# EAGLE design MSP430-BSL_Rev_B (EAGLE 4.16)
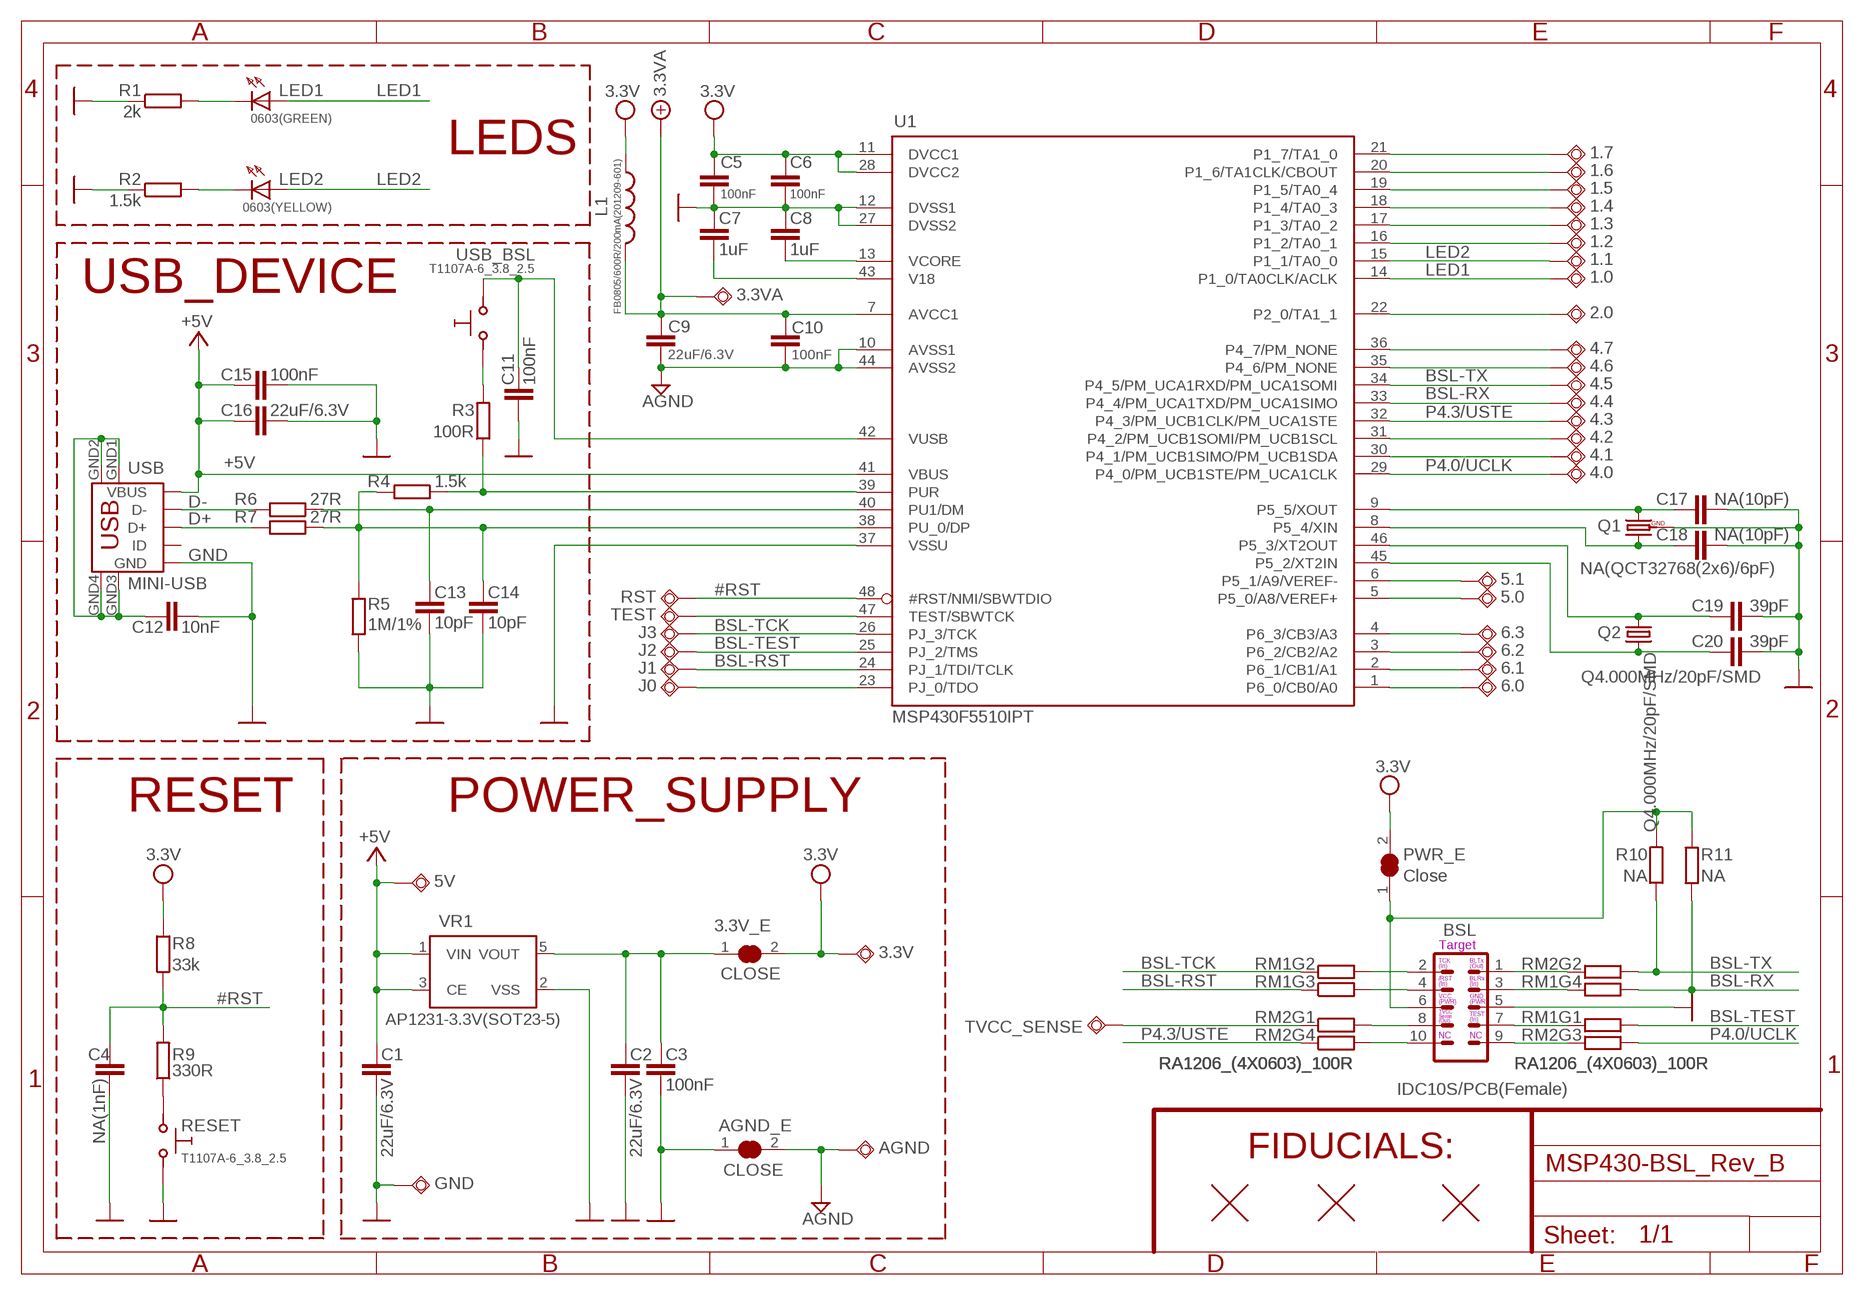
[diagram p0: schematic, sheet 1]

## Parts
1.0  TESTPAD80/50  [SMD80/50]
1.1  TESTPAD80/50  [SMD80/50]
1.2  TESTPAD80/50  [SMD80/50]
1.3  TESTPAD80/50  [SMD80/50]
1.4  TESTPAD80/50  [SMD80/50]
1.5  TESTPAD80/50  [SMD80/50]
1.6  TESTPAD80/50  [SMD80/50]
1.7  TESTPAD80/50  [SMD80/50]
2.0  TESTPAD80/50  [SMD80/50]
3.3V  TESTPAD80/50  [SMD80/50]
3.3V_E  CLOSE  SJSJ_1_SMALLER_CLOSE  [SJ_1_SMALLER_CLOSE]
3.3VA  TESTPAD80/50  [SMD80/50]
4.0  TESTPAD80/50  [SMD80/50]
4.1  TESTPAD80/50  [SMD80/50]
4.2  TESTPAD80/50  [SMD80/50]
4.3  TESTPAD80/50  [SMD80/50]
4.4  TESTPAD80/50  [SMD80/50]
4.5  TESTPAD80/50  [SMD80/50]
4.6  TESTPAD80/50  [SMD80/50]
4.7  TESTPAD80/50  [SMD80/50]
5.0  TESTPAD80/50  [SMD80/50]
5.1  TESTPAD80/50  [SMD80/50]
5V  TESTPAD80/50  [SMD80/50]
6.0  TESTPAD80/50  [SMD80/50]
6.1  TESTPAD80/50  [SMD80/50]
6.2  TESTPAD80/50  [SMD80/50]
6.3  TESTPAD80/50  [SMD80/50]
AGND  TESTPAD80/50  [SMD80/50]
AGND_E  CLOSE  SJSJ_1_SMALLER_CLOSE  [SJ_1_SMALLER_CLOSE]
BSL  IDC10S/PCB(Female)  ML10SMD_1  [ML10L_PADS_FEMAIL]
C1  22uF/6.3V  C-EUC0603_DWS  [C0603_DWS]
C2  22uF/6.3V  C-EUC0603_DWS  [C0603_DWS]
C3  100nF  C-EUC0603_DWS  [C0603_DWS]
C4  NA(1nF)  C-EUC0603_DWS  [C0603_DWS]
C5  100nF  C-EUC0603_DWS  [C0603_DWS]
C6  100nF  C-EUC0603_DWS  [C0603_DWS]
C7  1uF  C-EUC0603_DWS  [C0603_DWS]
C8  1uF  C-EUC0603_DWS  [C0603_DWS]
C9  22uF/6.3V  C-EUC0603_DWS  [C0603_DWS]
C10  100nF  C-EUC0603_DWS  [C0603_DWS]
C11  100nF  C-EUC0603_DWS  [C0603_DWS]
C12  10nF  C-EUC0603_DWS  [C0603_DWS]
C13  10pF  C-EUC0603_DWS  [C0603_DWS]
C14  10pF  C-EUC0603_DWS  [C0603_DWS]
C15  100nF  C-EUC0603_DWS  [C0603_DWS]
C16  22uF/6.3V  C-EUC0603_DWS  [C0603_DWS]
C17  NA(10pF)  C-EUC0603_DWS  [C0603_DWS]
C18  NA(10pF)  C-EUC0603_DWS  [C0603_DWS]
C19  39pF  C-EUC0603_DWS  [C0603_DWS]
C20  39pF  C-EUC0603_DWS  [C0603_DWS]
GND  TESTPAD80/50  [SMD80/50]
J0  TESTPAD80/50  [SMD80/50]
J1  TESTPAD80/50  [SMD80/50]
J2  TESTPAD80/50  [SMD80/50]
J3  TESTPAD80/50  [SMD80/50]
L1  FB0805/600R/200mA(201209-601)  L-USL0805_5MIL_DWS  [L0805_5MIL_DWS]
LED1  0603(GREEN)  LED0603DWS  [LED-0603]
LED2  0603(YELLOW)  LED0603DWS  [LED-0603]
PWR_E  Close  SJSJ_1_SMALLER_CLOSE  [SJ_1_SMALLER_CLOSE]
Q1  NA(QCT32768(2x6)/6pF)  Q_GND1  [TC26H_3_REPAIR_SMD]
Q2  Q4.000MHz/20pF/SMD  HC49/S1  [HC49/SMD2_THIN]
R1  2k  R-EU_R0603_5MIL_DWS  [R0603_5MIL_DWS]
R2  1.5k  R-EU_R0603_5MIL_DWS  [R0603_5MIL_DWS]
R3  100R  R-EU_R0603_5MIL_DWS  [R0603_5MIL_DWS]
R4  1.5k  R-EU_R0603_5MIL_DWS  [R0603_5MIL_DWS]
R5  1M/1%  R-EU_R0603_5MIL_DWS  [R0603_5MIL_DWS]
R6  27R  R-EU_R0603_5MIL_DWS  [R0603_5MIL_DWS]
R7  27R  R-EU_R0603_5MIL_DWS  [R0603_5MIL_DWS]
R8  33k  R-EU_R0603_5MIL_DWS  [R0603_5MIL_DWS]
R9  330R  R-EU_R0603_5MIL_DWS  [R0603_5MIL_DWS]
R10  NA  R-EU_R0603_5MIL_DWS  [R0603_5MIL_DWS]
R11  NA  R-EU_R0603_5MIL_DWS  [R0603_5MIL_DWS]
RESET  T1107A-6_3.8_2.5  SW-TAKT6  [SW-TAKT_6X3.5_SMD]
RM1  RA1206_(4X0603)_100R  R_MATRIX_4E  [R_MATRIX_4]
RM2  RA1206_(4X0603)_100R  R_MATRIX_4E  [R_MATRIX_4]
RST  TESTPAD80/50  [SMD80/50]
TEST  TESTPAD80/50  [SMD80/50]
TVCC_SENSE  TESTPAD80/50  [SMD80/50]
U1  MSP430F5510IPT  MSP430F5510  [S-PQFP-G48]
U$2  FIDUCIAL1X2  [FIDUCIAL-1X2]
U$500  FIDUCIAL1X2  [FIDUCIAL-1X2]
U$507  FIDUCIAL1X2  [FIDUCIAL-1X2]
USB  MINI-USB  MINI_USB9  [USB_MINI_9PIN]
USB_BSL  T1107A-6_3.8_2.5  SW-TAKT6  [SW-TAKT_6X3.5_SMD]
VR1  AP1231-3.3V(SOT23-5)  AP1231-33  [SOT-23-5]

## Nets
#RST: C4.2 R8.1 R9.2 RST.P$1(PP) U1.48(#RST/NMI/SBWTDIO)
+5V: 5V.P$1(PP) C1.1 C15.2 C16.2 U1.41(VBUS) USB.VBUS VR1.1(VIN) VR1.3(CE)
+8V: 3.3VA.P$1(PP) C9.1 C10.2 L1.2 U1.7(AVCC1) ; supply symbol labelled 3.3VA
AGND: AGND.P$1(PP) AGND_E.2 C9.2 C10.1 U1.10(AVSS1) U1.44(AVSS2)
BSL-RST: J1.P$1(PP) RM1.3.1 U1.24(PJ_1/TDI/TCLK)
BSL-RX: 4.4.P$1(PP) R11.2 RM1.4.1 U1.33(P4_4/PM_UCA1TXD/PM_UCA1SIMO)
BSL-TCK: J3.P$1(PP) RM1.2.1 U1.26(PJ_3/TCK)
BSL-TEST: J2.P$1(PP) RM1.1.1 U1.25(PJ_2/TMS)
BSL-TX: 4.5.P$1(PP) R10.2 RM2.2.1 U1.34(P4_5/PM_UCA1RXD/PM_UCA1SOMI)
D+: C14.2 R4.2 R5.1 R7.1 U1.38(PU_0/DP)
D-: C13.2 R6.1 U1.40(PU1/DM)
GND: AGND_E.1 BSL.5 C1.2 C2.2 C3.2 C4.1 C5.1 C6.1 C7.2 C8.2 C11.1 C12.1 C13.1 C14.1 C15.1 C16.1 C17.1 C18.1 C19.1 C20.1 GND.P$1(PP) Q1.GND R1.1 R2.1 R5.2 RESET.P$2 U1.12(DVSS1) U1.27(DVSS2) U1.37(VSSU) USB.GND VR1.2(VSS)
LED1: 1.0.P$1(PP) LED1.A U1.14(P1_0/TA0CLK/ACLK)
LED2: 1.1.P$1(PP) LED2.A U1.15(P1_1/TA0_0)
N$1: LED2.C R2.2
N$2: C19.2 Q2.1 U1.46(P5_3/XT2OUT)
N$3: BSL.10 RM2.4.2
N$4: BSL.8 RM2.1.2
N$5: R3.1 R4.1 U1.39(PUR)
N$6: BSL.9 RM2.3.2
N$7: 6.3.P$1(PP) U1.4(P6_3/CB3/A3)
N$8: C17.2 Q1.1 U1.9(P5_5/XOUT)
N$9: C18.2 Q1.2 U1.8(P5_4/XIN)
N$10: C20.2 Q2.2 U1.45(P5_2/XT2IN)
N$11: R9.1 RESET.P$1
N$12: BSL.1 RM2.2.2
N$13: LED1.C R1.2
N$14: BSL.2 RM1.2.2
N$15: BSL.3 RM1.4.2
N$16: BSL.4 RM1.3.2
N$17: 6.0.P$1(PP) U1.1(P6_0/CB0/A0)
N$18: R6.2 USB.D-
N$19: R3.2 USB_BSL.P$1
N$20: J0.P$1(PP) U1.23(PJ_0/TDO)
N$21: R7.2 USB.D+
N$22: BSL.7 RM1.1.2
N$23: RM2.1.1 TVCC_SENSE.P$1(PP)
P1.2: 1.2.P$1(PP) U1.16(P1_2/TA0_1)
P1.3: 1.3.P$1(PP) U1.17(P1_3/TA0_2)
P1.4: 1.4.P$1(PP) U1.18(P1_4/TA0_3)
P1.5: 1.5.P$1(PP) U1.19(P1_5/TA0_4)
P1.6: 1.6.P$1(PP) U1.20(P1_6/TA1CLK/CBOUT)
P1.7: 1.7.P$1(PP) U1.21(P1_7/TA1_0)
P2.0: 2.0.P$1(PP) U1.22(P2_0/TA1_1)
P4.0/UCLK: 4.0.P$1(PP) RM2.3.1 U1.29(P4_0/PM_UCB1STE/PM_UCA1CLK)
P4.1: 4.1.P$1(PP) U1.30(P4_1/PM_UCB1SIMO/PM_UCB1SDA)
P4.2: 4.2.P$1(PP) U1.31(P4_2/PM_UCB1SOMI/PM_UCB1SCL)
P4.3/USTE: 4.3.P$1(PP) RM2.4.1 U1.32(P4_3/PM_UCB1CLK/PM_UCA1STE)
P4.6: 4.6.P$1(PP) U1.35(P4_6/PM_NONE)
P4.7: 4.7.P$1(PP) U1.36(P4_7/PM_NONE)
P5.0: 5.0.P$1(PP) U1.5(P5_0/A8/VEREF+)
P5.1: 5.1.P$1(PP) U1.6(P5_1/A9/VEREF-)
P6.1: 6.1.P$1(PP) U1.2(P6_1/CB1/A1)
P6.2: 6.2.P$1(PP) U1.3(P6_2/CB2/A2)
TARGET_PWR: BSL.6 PWR_E.1 R10.1 R11.1
TEST: TEST.P$1(PP) U1.47(TEST/SBWTCK)
USB_SHIELD: C12.2 USB.GND1 USB.GND2 USB.GND3 USB.GND4
V18: C7.1 U1.43(V18)
VCC: 3.3V.P$1(PP) 3.3V_E.2 C5.2 C6.2 L1.1 PWR_E.2 R8.2 U1.11(DVCC1) U1.28(DVCC2) ; supply symbol labelled 3.3V
VCORE: C8.1 U1.13(VCORE)
VOUT: 3.3V_E.1 C2.1 C3.1 VR1.5(VOUT)
VUSB: C11.2 U1.42(VUSB) USB_BSL.P$2
Unconnected: USB.ID

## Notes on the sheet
- LEDS
- USB_DEVICE
- Q4.000MHz/20pF/SMD
- RESET | POWER_SUPPLY
- Target
- TCK | BLTx
- (In) | (Out)
- /RST | BLRx
- (In) | (In)
- VCC | GND
- (PWR) | (PWR)
- TVCC
- TEST
- Sense
- (Out) | (In)
- NC | NC
- FIDUCIALS:

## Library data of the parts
1.0 1.1-1.7 2.0 3.3V 3.3VA 4.0 4.1-4.7 5.0 5.1 5V 6.0 6.1-6.3 AGND GND J0 J1-J3 RST TEST TVCC_SENSE = gogo:TESTPAD: drill 40mils, diameter 70mils
3.3V_E AGND_E PWR_E = jumper:SJ: SMD solder JUMPER
BSL = con-harting-ml:ML10: HARTING
C1-C20 = rcl:C-EU: CAPACITOR, European symbol
L1 = rcl:L-US: INDUCTOR, American symbol
LED1 LED2 = DOUBLE-SIDE:LED
Q1 = crystal:Q_GND
Q2 = crystal:HC49/S: CRYSTAL
R1-R11 = rcl:R-EU_: RESISTOR, European symbol
RESET USB_BSL = gogo:SW-TAKT
RM1 RM2 = OLIMEX_DISCRET:R_MATRIX_4E
U1 = OLIMEX_IC:MSP430F5510
U$2 U$500 U$507 = SparkFunEagle-6-6-07:FIDUCIAL: Fiducial Alignment Points
USB = OLIMEX_CONNECTORS:MINI_USB9
VR1 = OLIMEX_DISCRET:AP1231

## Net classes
0 default: width 0.2 mm, drill 0.2 mm
1 pwr: width 0.35 mm, drill 0.25 mm
2 thin: width 0.025 mm, drill 0.025 mm

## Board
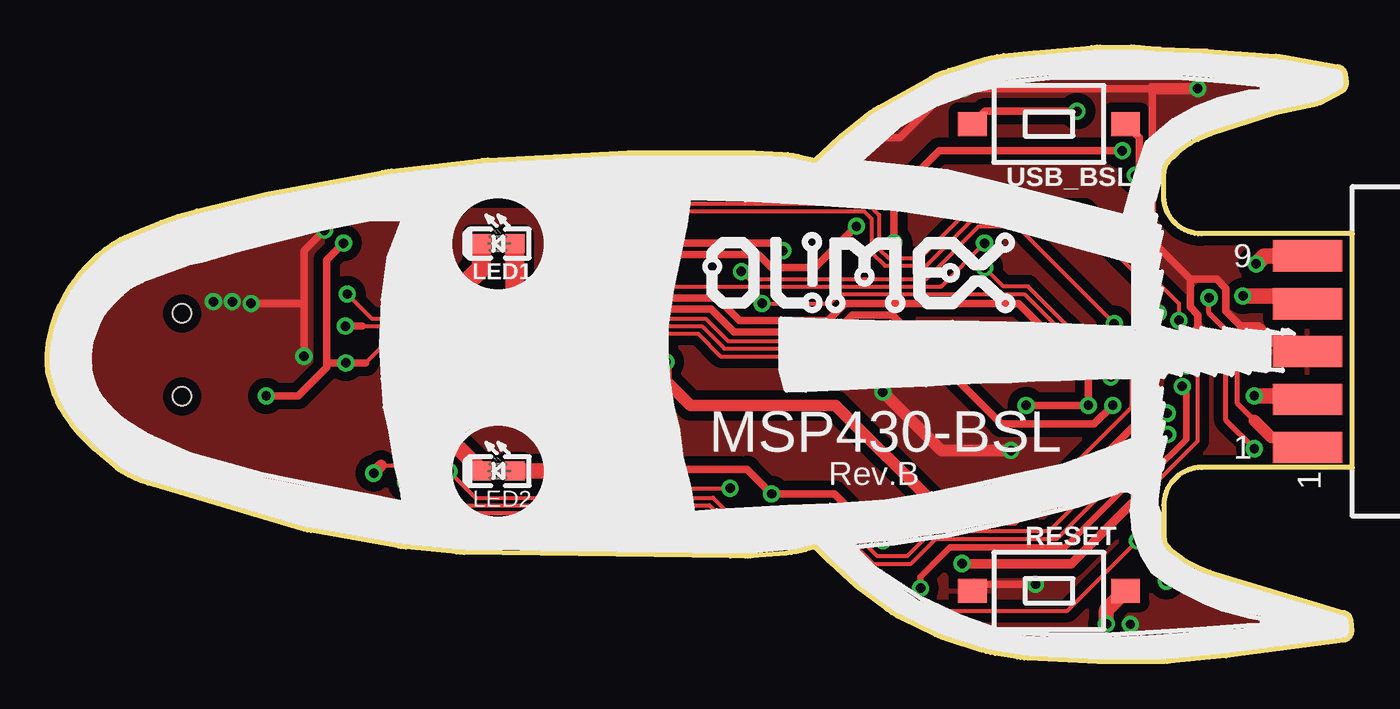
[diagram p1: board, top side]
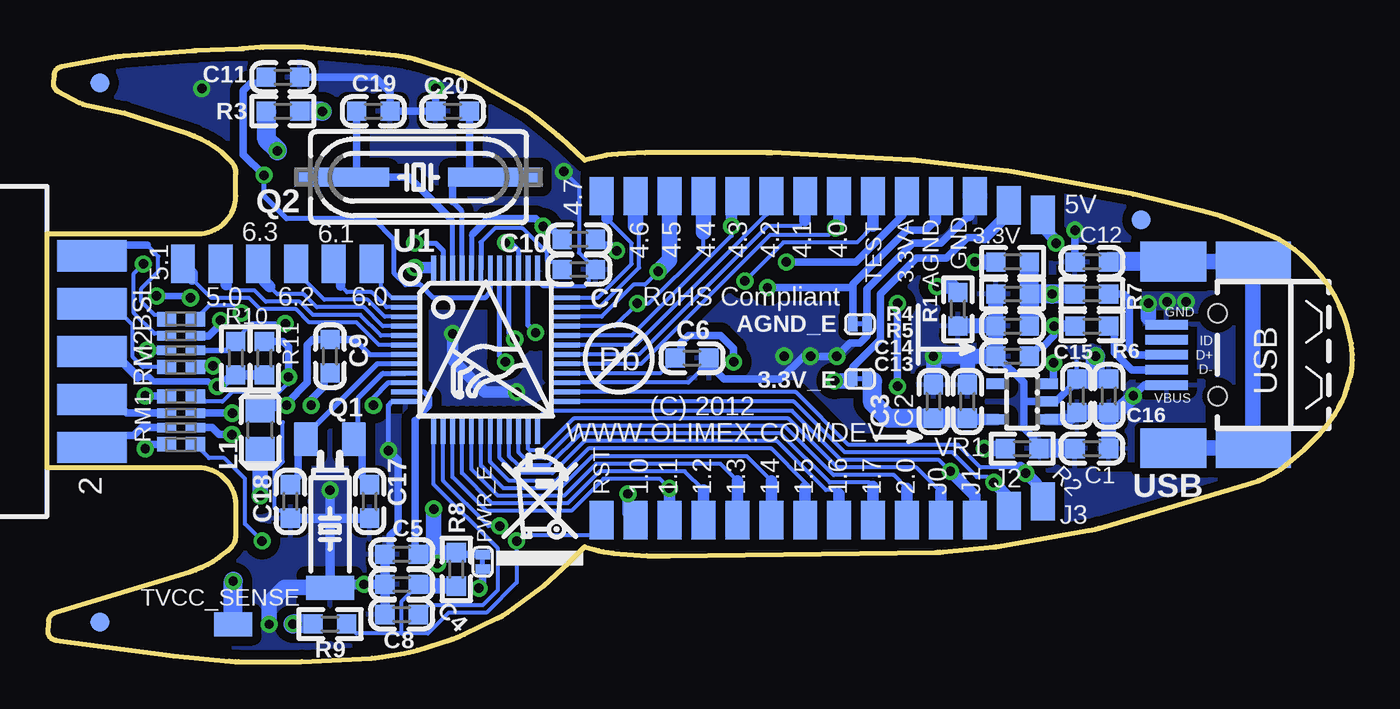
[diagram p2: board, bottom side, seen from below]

Size 69.22 x 32.6 mm. Coordinates in mm from the lower left corner, seen from the top.
Outline: 101 segments
Copper layers (1+16): Top 0.035mm / dielectric 1.5mm / Bottom 0.035mm
Design rules "default": minimum track width 0.2mm, minimum drill 0.5mm, track to track 0.2mm, track to pad 0.2mm, pad to pad 0.2mm, via to via 0.2mm, smd to smd 1mil, copper to edge 10mil, drill to drill 8mil, minimum pad ring 10mil, minimum via ring 8mil, stop-mask expansion 4mil, vias tented up to drill 25mil, thermal gap 20mil
bRestrict: 1 lines

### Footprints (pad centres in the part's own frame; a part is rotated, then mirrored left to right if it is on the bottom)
SMD80/50 = smd 2.032 x 1.27: P$1 0,0
SJ_1_SMALLER_CLOSE = smd 0.508 x 0.762: 1 -0.381,0; 2 0.381,0
ML10L_PADS_FEMAIL = smd 1.651 x 3.683 bottom: 1 -5.093,-3.404; 3 -2.553,-3.404; 5 -0.013,-3.404; 7 2.527,-3.404; 9 5.067,-3.404 | smd 1.651 x 3.683: 2 -5.093,-3.404; 4 -2.553,-3.404; 6 -0.013,-3.404; 8 2.527,-3.404; 10 5.067,-3.404
C0603_DWS = smd 1.016 x 1.016: 1 -0.889,0; 2 0.889,0
L0805_5MIL_DWS = smd 1.27 x 1.524: 1 -1.016,0; 2 1.016,0
LED-0603 = smd 1.016 x 1.016: A 0.889,0; C -0.889,0
TC26H_3_REPAIR_SMD = smd 1.27 x 1.778: 1 -1.27,0; 2 1.27,0 | smd 2.54 x 1.27: GND 0,7.874
HC49/SMD2_THIN = smd 5 x 1: 1 -4.064,0; 2 4.064,0
R0603_5MIL_DWS = smd 1.016 x 1.016: 1 -0.889,0; 2 0.889,0
SW-TAKT_6X3.5_SMD = smd 1.27 x 1.524: P$1 0,4.064; P$2 0,-4.064
R_MATRIX_4 = smd 1.016 x 0.762: 1.1 -0.762,1.27; 1.2 0.762,1.27; 4.1 -0.762,-1.27; 4.2 0.762,-1.27 | smd 1.016 x 0.508: 2.1 -0.762,0.381; 2.2 0.762,0.381; 3.1 -0.762,-0.381; 3.2 0.762,-0.381
S-PQFP-G48 = smd 0.254 x 1.5: 1 -2.75,-4.25; 2 -2.25,-4.25; 3 -1.75,-4.25; 4 -1.25,-4.25; 5 -0.75,-4.25; 6 -0.25,-4.25; 7 0.25,-4.25; 8 0.75,-4.25; 9 1.25,-4.25; 10 1.75,-4.25; 11 2.25,-4.25; 12 2.75,-4.25; 25 2.75,4.25; 26 2.25,4.25; 27 1.75,4.25; 28 1.25,4.25; 29 0.75,4.25; 30 0.25,4.25; 31 -0.25,4.25; 32 -0.75,4.25; 33 -1.25,4.25; 34 -1.75,4.25; 35 -2.25,4.25; 36 -2.75,4.25 | smd 1.5 x 0.254: 13 4.25,-2.75; 14 4.25,-2.25; 15 4.25,-1.75; 16 4.25,-1.25; 17 4.25,-0.75; 18 4.25,-0.25; 19 4.25,0.25; 20 4.25,0.75; 21 4.25,1.25; 22 4.25,1.75; 23 4.25,2.25; 24 4.25,2.75; 37 -4.25,2.75; 38 -4.25,2.25; 39 -4.25,1.75; 40 -4.25,1.25; 41 -4.25,0.75; 42 -4.25,0.25; 43 -4.25,-0.25; 44 -4.25,-0.75; 45 -4.25,-1.25; 46 -4.25,-1.75; 47 -4.25,-2.25; 48 -4.25,-2.75
FIDUCIAL-1X2 = smd 1 x 1: 1 0,0
USB_MINI_9PIN = smd 2.25 x 0.5: D+ 2.706,0; D- 2.706,0.8; GND 2.706,-1.6; ID 2.706,-0.8; VBUS 2.706,1.6 | smd 4 x 2.1: GND1 -1.9,4.95; GND3 -1.9,-4.95 | smd 3.5 x 2.1: GND2 2.35,4.95; GND4 2.35,-4.95 | hole 1: 0,2.2; 0,-2.2
SOT-23-5 = smd 0.55 x 1.2: 1 -0.95,-1.3; 2 0,-1.3; 3 0.95,-1.3; 4 0.95,1.3; 5 -0.95,1.3

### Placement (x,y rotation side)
1.0  38.02,7.5 90 bottom
1.1  36.22,7.5 90 bottom
1.2  34.42,7.5 90 bottom
1.3  32.62,7.5 90 bottom
1.4  30.82,7.5 90 bottom
1.5  29.02,7.5 90 bottom
1.6  27.22,7.5 90 bottom
1.7  25.42,7.5 90 bottom
2.0  23.62,7.5 90 bottom
3.3V  18.22,24.2 90 bottom
3.3V_E  26.12,15 180 bottom
3.3VA  23.62,24.7 90 bottom
4.0  27.22,24.7 270 bottom
4.1  29.02,24.7 270 bottom
4.2  30.82,24.7 270 bottom
4.3  32.62,24.7 270 bottom
4.4  34.42,24.7 270 bottom
4.5  36.22,24.7 270 bottom
4.6  38.02,24.7 270 bottom
4.7  39.82,24.7 270 bottom
5.0  60.02,21.1 270 bottom
5.1  62.02,21.1 270 bottom
5V  16.42,23.7 90 bottom
6.0  52.02,21.1 270 bottom
6.1  54.02,21.1 270 bottom
6.2  56.02,21.1 270 bottom
6.3  58.02,21.1 270 bottom
AGND  21.82,24.7 90 bottom
AGND_E  26.12,17.9 180 bottom
BSL  70.23,16.46 90 bottom
C1  13.82,11.3 180 bottom
C2  20.42,13.8 90 bottom
C3  22.22,13.8 90 bottom
C4  50.42,4.1 0 bottom
C5  50.42,5.7 0 bottom
C6  35.02,16.1 180 bottom
C7  41.02,20.8 0 bottom
C8  50.42,2.5 180 bottom
C9  54.22,16.2 270 bottom
C10  41.02,22.4 0 bottom
C11  56.72,31 180 bottom
C12  13.82,21.2 0 bottom
C13  18.02,16.2 0 bottom
C14  18.02,17.8 0 bottom
C15  14.62,14.1 270 bottom
C16  12.92,14.1 270 bottom
C17  52.12,8.5 90 bottom
C18  56.32,8.5 90 bottom
C19  51.92,29.2 180 bottom
C20  47.72,29.2 0 bottom
GND  20.02,24.7 90 bottom
J0  21.82,7.5 270 bottom
J1  20.02,7.5 270 bottom
J2  18.22,8 270 bottom
J3  16.42,8.5 270 bottom
L1  57.92,12.3 90 bottom
LED1  23.92,22.18 0 top
LED2  23.92,10.11 0 top
PWR_E  46.12,5.3 90 bottom
Q1  54.22,11.8 180 bottom
Q2  49.52,25.7 0 bottom
R1  20.92,18.7 90 bottom
R2  17.52,11.3 180 bottom
R3  56.72,29.2 0 bottom
R4  18.02,21.2 0 bottom
R5  18.02,19.5 180 bottom
R6  13.82,17.8 0 bottom
R7  13.82,19.5 0 bottom
R8  47.52,4.9 90 bottom
R9  54.22,2 0 bottom
R10  59.22,16.1 90 bottom
R11  57.69,16.1 90 bottom
RESET  53.13,3.76 270 top
RM1  62.12,12.8 180 bottom
RM2  62.12,16.9 180 bottom
RST  39.82,7.5 90 bottom
TEST  25.42,24.7 90 bottom
TVCC_SENSE  59.35,1.98 180 bottom
U1  45.97,16.55 270 bottom
U$1  [ESD_SYMBOL]  49.52,13.03 0 bottom
U$2  66.42,30.7 0 bottom
U$4  [PB_SMALL]  38.9,16.08 0 bottom
U$5  [RECYCLE_BIN1/8]  45.38,5.12 0 bottom
U$9  [OLIMEX1_V]  52.49,18.36 0 top
U$500  11.22,23.45 0 bottom
U$507  66.42,2.1 0 bottom
USB  7.15,16.27 180 bottom
USB_BSL  53.13,28.53 90 top
VR1  17.52,13.8 90 bottom

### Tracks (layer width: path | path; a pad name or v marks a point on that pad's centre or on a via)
#RST  (via drill 0.5)
  Top 0.2: v44.32,6.4 45.82,6.4 46.74,7.32 51.34,7.32 57.52,13.5 57.52,15.2 56.62,16.1 55.82,16.1 52.02,19.9 50.72,19.9 v49.72,20.9
  Bottom 0.2: C4.2 50.42,3.21 50.42,1.5 | 50.42,1.5 52.83,1.5 R9.2 | 50.42,1.5 49.02,1.5 47.92,2.6 45.92,2.6 44.32,4.2 v44.32,6.4 44.02,6.7 40.32,6.7 39.82,7.2 RST.P$1
  Bottom 0.254: 48.94,20.9 48.82,20.9 U1.48
  Bottom 0.4: R8.1 47.23,4.3
  Bottom 0.61: v49.72,20.9 48.94,20.9
  Bottom 0.813: R8.1 48.93,4.01 49.02,4.1 C4.2
+5V  (via drill 0.5)
  Top 0.2: v44.92,15.9 44.02,15.9 43.72,16.2 35.72,16.2 34.52,17.4 18.44,17.4 16.89,15.85
  Top 0.4: 14.82,15.85 v15.84,15.85 16.89,15.85 | 14.82,15.85 14.82,15.6 13.32,14.1 v11.62,14.1 | 14.82,15.85 14.82,21.3 v15.72,22.2
  Bottom 0.2: C1.1
  Bottom 0.254: U1.41 45.22,16.2 v44.92,15.9
  Bottom 0.406: USB.VBUS 11.04,14.68 v11.62,14.1 | VR1.3 15.97,14.75 15.84,14.87 v15.84,15.85
  Bottom 0.6: VR1.1 14.98,12.85 C15.2
  Bottom 0.61: 5V.P$1 16.42,23.05 15.72,22.35 v15.72,22.2
  Bottom 0.8: C16.2 C15.2 | C16.2 12.51,13.21 v11.62,14.1 | C1.1 C16.2
  pour Bottom (isolate 0.3): 7.92,14.9 11.72,14.9 12.82,13.8 15.12,13.8 15.12,12.8 14.32,12 13.42,12 13.42,10.7 9.52,10.7 7.92,12.3
+8V  (via drill 0.5)
  Top 0.4: v56.52,13.6 55.52,12.6 50.62,12.6 44.82,18.4 42.72,18.4 41.82,17.5 36.42,17.5 35.22,18.7 30.42,18.7 30.02,19.1 v30.02,21.2 31.02,22.2 38.62,22.2 v39.02,21.8
  Bottom 0.254: U1.7 52.12,16.3 52.91,17.09
  Bottom 0.4: 52.91,17.09 C9.1 55.13,17.09 55.42,16.8 55.42,14.8 56.52,13.7 v56.52,13.6 | v30.02,21.2 26.32,21.2 23.94,23.57 23.94,23.73 | C10.2 39.83,22.1 39.32,22.1 v39.02,21.8
  Bottom 0.6: 23.94,23.73 23.94,24.38 3.3VA.P$1
  Bottom 0.61: v56.52,13.6 57.63,13.6 L1.2
AGND  (via drill 0.5)
  Top 0.4: v51.92,13.6 v55.22,13.6 55.22,15.3 51.52,19 42.32,19 41.42,18.1 36.72,18.1 35.52,19.3 31.56,19.3 v31.02,19.85 31.02,20.4 32.22,21.6 37.72,21.6 38.42,20.9 40.72,20.9 v42.92,23.1
  Bottom 0.254: U1.10 51.12,14.8 51.92,14 v51.92,13.6 | 46.64,22.7 46.72,22.62 U1.44
  Bottom 0.4: AGND_E.2 26.5,19.85 | 26.5,19.85 v31.02,19.85 | 26.5,19.85 26.5,20.02 23.62,22.9 22.62,22.9 22.12,23.4 | 46.64,22.7 45.83,23.5 43.32,23.5 v42.92,23.1 42.61,23.1 C10.1 | C9.2 54.52,15.01 54.52,14.61 55.22,13.91 v55.22,13.6
  Bottom 0.6: AGND.P$1 22.12,24.4 22.12,23.4
BSL-RST  (via drill 0.5)
  Top 0.2: v21.32,10.1 22.72,8.7 35.32,8.7 36.12,7.9 41.72,7.9 44.02,5.6 45.62,5.6 46.94,6.92 53.14,6.92 v59.4,13.18
  Bottom 0.2: v21.32,10.1 21.92,10.7 27.12,10.7 29.72,13.3 42.82,13.3 43.22,12.9 U1.24
  Bottom 0.406: v59.4,13.18 RM1.3.1
  Bottom 0.6: J1.P$1 20.02,8.8
  Bottom 0.61: 20.02,8.8 v21.32,10.1
BSL-RX  (via drill 0.5)
  Top 0.2: v37.92,19 41.52,19 42.02,19.5 51.82,19.5 56.22,15.1 v56.42,15.1
  Bottom 0.2: 34.42,22.8 34.42,21.9 37.32,19 v37.92,19 39.12,17.8 U1.33 | RM1.4.1 61.09,14.07 60.82,13.8 59.92,13.8 59.42,14.3 56.92,14.3 56.42,14.8
  Bottom 0.406: R11.2 56.71,16.99 56.42,16.7 v56.42,15.1 56.42,14.8
  Bottom 0.813: 34.42,22.8 4.4.P$1
BSL-TCK  (via drill 0.5)
  Top 0.2: 17.72,10.4 19.72,10.4 21.82,8.3 35.12,8.3 35.92,7.5 41.52,7.5 43.82,5.2 45.82,5.2 47.14,6.52 53.54,6.52 59.07,12.05 v59.42,12.05
  Top 0.61: v17.32,10 17.72,10.4
  Bottom 0.2: 17.62,10.3 19.72,10.3 20.92,11.5 26.72,11.5 29.52,14.3 U1.26
  Bottom 0.406: v59.42,12.05 60.09,12.05 60.46,12.42 RM1.2.1
  Bottom 0.6: J3.P$1 16.77,8.85 16.77,9.45 v17.32,10 17.62,10.3
BSL-TEST  (via drill 0.5)
  Top 0.2: 20.62,7.9 34.92,7.9 35.72,7.1 41.32,7.1 43.62,4.8 44.22,4.8 46.32,2.7 54.12,2.7 v57.82,6.4
  Top 0.61: v19.02,9.5 20.62,7.9
  Bottom 0.2: U1.25 29.62,13.8 26.92,11.1 21.22,11.1 19.92,9.8 19.32,9.8 v19.02,9.5 | RM1.1.1 60.62,10.8 59.82,10.8 58.72,9.7 58.72,7.3 v57.82,6.4
  Bottom 0.6: J2.P$1 18.22,8.7 v19.02,9.5
BSL-TX  (via drill 0.5)
  Top 0.2: v56.59,17.93 51.42,23.1 49.42,23.1 46.62,20.3 37.22,20.3 v36.82,20.7
  Bottom 0.2: U1.34 39.82,18.3 38.12,20 37.52,20 v36.82,20.7 | R10.2 58.82,17.39 58.82,17.5 58.39,17.93 v56.59,17.93
  Bottom 0.305: R10.2 59.69,16.52 RM2.2.1
  Bottom 0.813: v36.82,20.7 36.22,21.3 4.5.P$1
D+  (via drill 0.5)
  Top 0.2: v15.92,19.5 17.22,18.2 34.92,18.2 36.12,17 42.87,17 v43.32,17.45
  Bottom 0.254: U1.38 43.72,17.85 v43.32,17.45
  Bottom 1.016: R5.1 C14.2 | R5.1 R4.2 | R7.1 v15.92,19.5 R5.1
D-  (via drill 0.5)
  Top 0.2: 16.72,17.8 34.72,17.8 35.92,16.6 43.92,16.6 v44.42,17.1
  Top 0.4: v15.82,17.8 16.72,17.8
  Bottom 0.254: U1.40 44.72,17.4 v44.42,17.1
  Bottom 0.4: C13.2 16.63,16.7 16.42,16.7 15.82,17.3 v15.82,17.8
  Bottom 0.61: R6.1 v15.82,17.8
GND  (via drill 0.5)
  Top 0.4: v13.62,16.2 13.62,19 | 13.62,19 v10.82,19 | 13.62,19 13.62,21.8 v14.71,22.89 16.12,24.3 20.72,24.3 22.02,25.6 41.42,25.6 v41.82,26 43.62,27.8 45.22,27.8 47.82,30.4 v48.61,30.4 58.62,30.4 58.62,22.3 60.62,20.3 | RESET.P$2 49.4,4.1 v52.42,4.1 | v54.22,9.1 58.32,13.2 58.32,15.02 61.02,17.72 61.02,18.4 60.62,18.8 60.62,20.3 | 60.62,20.3 62.02,20.3 62.52,19.8 62.52,18.6 63.42,17.7
  Top 0.6: 63.42,17.7 64.22,17.7 64.92,17 66.28,17 BSL.5 | v51.12,11.2 47.42,11.2 v44.32,14.3 | 58.62,30.4 v61.02,30.4
  Top 0.8: v22.22,16.2 v27.34,16.2
  Bottom 0.2: 34.52,15.5 35.22,14.8 U1.27 | U1.37 43.22,20.2 42.92,19.9 40.72,19.9 40.52,20.1 40.52,20.41 C7.2 41.02,21.69 41.02,25.2 v41.82,26 | R5.2 19.02,19.5 | R1.1 | C3.2 | 14.62,15.9 C15.1 14.62,14.9 | 16.92,11.59 16.92,11.9 | GND.P$1 20.02,25.6 | C18.1 56.71,8 57.02,8 57.14,8.12 57.14,10.18 56.72,10.6 56.72,12.7
  Bottom 0.254: U1.12 50.92,13.8 51.12,13.6 v51.12,11.2
  Bottom 0.4: 34.13,15.5 34.52,15.5 | 20.34,23.68 21.82,22.2 23.29,22.2 25.74,19.76 AGND_E.1 25.74,17.28 26.12,16.9 26.64,16.9 v27.34,16.2 29.12,16.2 30.32,15 33.32,15 33.82,15.5 34.13,15.5 | v51.12,11.2 50.62,10.7 50.62,7.1 51.02,6.7 51.02,5.99 C5.1 | v48.61,30.4 C20.1 C19.1 51.03,30.21 51.82,31 C11.1 | 14.62,14.9 15.72,13.8 VR1.2 17.42,13.8 | 17.42,13.8 17.42,14.8 18.82,16.2 C13.1 | R2.1 16.92,11.59 | 16.92,11.9 17.42,12.4 17.42,13.8 | 13.62,14.99 C16.1 | v14.71,22.89 C12.1 | 34.13,15.5 C6.1
  Bottom 0.406: 10.82,18.26 10.71,18.26 10.71,17.88 USB.GND
  Bottom 0.5: 54.22,7.61 C18.1 | C4.1 C5.1 | C4.1 C8.2 | C4.1 v52.42,4.1 54.22,4.1 | 54.22,7.61 C17.1 | 54.22,7.61 54.22,4.1 | v54.22,9.1 54.22,7.61 | 54.22,4.1 Q1.GND
  Bottom 0.6: 20.34,23.68 20.34,24.38 GND.P$1 | Q1.GND | v47.72,17.4 47.72,16 46.02,14.3 v44.32,14.3
  Bottom 0.8: C14.1 R5.2 | C14.1 C13.1 20.42,16.2 | C14.1 R1.1 | 20.42,16.2 C2.2 | 20.42,16.2 v22.22,16.2 C3.2
  Bottom 0.813: v10.82,19 10.82,18.26 | Q1.GND 56.63,3.93 57.44,3.12 v57.44,1.98
  Bottom 1.016: C15.1 13.62,14.99 v13.62,16.2 | C1.2 R2.1
  other vias: 9.82,19.1 8.82,19.1 28.73,16.2 30.13,16.2
  pour Top (isolate 0.508, rank 2): 70.52,-1.7 -4.98,-1.7 -4.98,34.3 70.52,34.3
  pour Bottom (isolate 0.508, rank 2): 69.52,-0.7 -3.98,-0.7 -3.98,33.3 69.52,33.3
LED1  (via drill 0.5)
  Top 0.406: v45.22,7.2 45.12,7.3 43.35,7.3 41.75,8.9 v38.42,8.9 37.12,10.2 28.52,10.2 v24.12,14.6
  Top 0.813: v24.12,19 24.81,19.69
  Top 1.016: 24.81,19.69 LED1.A
  Bottom 0.2: v45.22,7.2 45.82,7.2 48.22,9.6 U1.14
  Bottom 0.4: v24.12,14.6 v24.12,19
  Bottom 0.6: 1.0.P$1 38.42,7.9 v38.42,8.9
LED2  (via drill 0.5)
  Top 0.2: v36.22,9.2 28.08,9.2 27.17,10.11
  Top 0.813: LED2.A 27.17,10.11
  Bottom 0.2: U1.15 47.72,9.8 45.92,8 41.42,8 39.72,9.7 36.72,9.7 v36.22,9.2
  Bottom 0.6: v36.22,9.2 1.1.P$1
N$1  (via drill 0.5)
  Top 0.813: LED2.C 21.84,11.3 v19.52,11.3
  Bottom 0.813: R2.2 v19.52,11.3
N$2
  Bottom 0.254: U1.46 47.72,23.4 47.82,23.5
  Bottom 0.4: 52.81,25.7 50.02,25.7 47.82,23.5 | 52.81,25.7 C19.2 | 52.81,25.7 Q2.1
N$3
  Bottom 0.2: RM2.4.2 63.11,18.4 63.52,18.4 64.22,19.1 64.22,19.8 63.32,20.7 63.32,21.5 63.92,22.1
  Bottom 0.406: 63.92,22.1 66.26,22.1 BSL.10
N$4
  Bottom 0.2: RM2.1.2 64.15,15.63 64.67,16.15 64.67,17.85 65.8,18.99 BSL.8
N$5  (via drill 0.5)
  Top 0.2: 20.02,22.5 22.22,24.7 44.92,24.7
  Top 0.406: v57.02,27.1 47.32,27.1 44.92,24.7 v44.92,22.23
  Top 0.813: v20.02,21.2 20.02,22.5
  Bottom 0.2: v44.92,22.23 44.64,22.23
  Bottom 0.254: 44.64,22.23 44.22,21.8 U1.39
  Bottom 0.813: R4.1 v20.02,21.2
  Bottom 1.016: R3.1 57.57,29.16 57.57,27.7 57.02,27.15 v57.02,27.1
N$6  (via drill 0.5)
  Top 0.813: BSL.9 64.54,21.53 v64.12,21.1
  Bottom 0.2: RM2.3.2 63,17.4 63.52,17.4 64.62,18.5 64.62,20.6 v64.12,21.1
N$7
  Bottom 0.2: 57.42,19.9 57.02,19.5 55.62,19.5 54.92,18.8 52.42,18.8 51.42,17.8 U1.4
  Bottom 0.6: 6.3.P$1 57.74,20.82 57.74,20.23 57.42,19.9
N$8
  Bottom 0.2: Q1.1 52.72,12.03
  Bottom 0.254: 52.72,12.03 52.72,14 51.42,15.3 U1.9
  Bottom 0.4: Q1.1 52.52,11.37 52.52,9.79 C17.2
N$9
  Bottom 0.2: 55.02,12.5 55.02,12.27 Q1.2
  Bottom 0.254: U1.8 51.72,15.8 55.02,12.5
  Bottom 0.4: Q1.2 55.92,11.37 55.92,9.79 C18.2
N$10
  Bottom 0.254: U1.45 47.22,23.9 47.72,24.4
  Bottom 0.4: 47.72,24.4 47.72,25.3 47.32,25.7 46.83,25.7 | 46.83,25.7 C20.2 | 46.83,25.7 Q2.2
N$11  (via drill 0.5)
  Top 0.8: RESET.P$1 56.18,2.75 v56.18,2
  Bottom 1.016: R9.1 v56.18,2
N$12  (via drill 0.5)
  Top 0.254: v63.9,16.52 63.12,15.74 63.12,13.7 64.02,12.8
  Top 0.6: 64.02,12.8 64.92,11.9 66.3,11.9 BSL.1
  Bottom 0.406: v63.9,16.52 RM2.2.2
N$13  (via drill 0.5)
  Top 1.016: v22.02,19.9 23.03,20.91 LED1.C
  Bottom 0.8: R1.2 21.23,19.9 v22.02,19.9
N$14
  Bottom 0.406: BSL.2 66.2,12 64.62,12 64.2,12.42 RM1.2.2
N$15  (via drill 0.5)
  Top 0.813: v64.02,14.1 66.64,14.1 BSL.3
  Bottom 0.2: RM1.4.2 62.91,14.1
  Bottom 0.406: 62.91,14.1 v64.02,14.1
N$16
  Bottom 0.2: 65.72,13.91 BSL.4
  Bottom 0.406: RM1.3.2 65,13.18 65.72,13.91
N$17
  Bottom 0.2: 6.0.P$1 51.52,20.6 51.52,19.9 50.92,19.3 U1.1
N$18
  Bottom 0.4: USB.D- 11.69,15.48 12.62,16.4 12.62,17.49 R6.2
N$19  (via drill 0.5)
  Top 0.4: USB_BSL.P$1 49.74,29.2 v54.62,29.2
  Bottom 1.016: v54.62,29.2 R3.2
N$20
  Bottom 0.2: 21.82,9 23.12,10.3 27.32,10.3 29.92,12.9 41.29,12.9 42.99,11.2 43.62,11.2 43.72,11.3 U1.23
  Bottom 0.6: J0.P$1 21.82,9
N$21
  Bottom 0.4: USB.D+ 11.49,16.27 11.82,16.6 11.82,19.2 12.12,19.5 R7.2
N$22  (via drill 0.5)
  Top 0.254: v64.02,11.3 62.52,12.8 62.52,17.6 61.62,18.5 v61.62,19.3
  Top 0.813: v63.42,19.4 66.42,19.4 BSL.7
  Bottom 0.35: v61.62,19.3 61.72,19.4 v63.42,19.4
  Bottom 0.406: v64.02,11.3 63.79,11.53 RM1.1.2
N$23  (via drill 0.5)
  Top 0.2: 58.72,5.5 58.72,9.4 61.02,11.7 61.02,15.1 v60.42,15.7
  Top 0.4: v59.35,4.27 58.72,4.9 58.72,5.5
  Bottom 0.4: 61.28,15.7 RM2.1.1
  Bottom 0.61: v60.42,15.7 61.28,15.7
  Bottom 1.016: TVCC_SENSE.P$1 v59.35,4.27
P1.2
  Bottom 0.2: U1.16 47.22,10 45.62,8.4 41.62,8.4 39.92,10.1 35.42,10.1 34.42,9.1
  Bottom 0.6: 1.2.P$1 34.42,9.1
P1.3
  Bottom 0.2: U1.17 46.72,10.2 45.32,8.8 41.82,8.8 40.12,10.5 33.52,10.5 32.62,9.6
  Bottom 0.6: 1.3.P$1 32.62,9.6
P1.4
  Bottom 0.2: U1.18 46.22,10.4 45.02,9.2 42.02,9.2 40.32,10.9 32.12,10.9 30.82,9.6
  Bottom 0.6: 1.4.P$1 30.82,9.6
P1.5
  Bottom 0.2: U1.19 45.72,10.6 44.72,9.6 42.22,9.6 40.52,11.3 30.82,11.3 29.02,9.5 29.02,9.25
  Bottom 0.6: 1.5.P$1 29.02,9.25
P1.6
  Bottom 0.2: U1.20 45.22,10.8 44.42,10 42.42,10 40.72,11.7 30.52,11.7 27.92,9.1 27.42,9.1 27.22,8.9
  Bottom 0.6: 1.6.P$1 27.22,8.9
P1.7
  Bottom 0.2: 25.42,9.3 25.62,9.5 27.72,9.5 30.32,12.1 40.92,12.1 42.62,10.4 44.22,10.4 44.72,10.9 U1.21
  Bottom 0.6: 1.7.P$1 25.42,9.3
P2.0
  Bottom 0.2: 23.62,9.2 24.32,9.9 27.52,9.9 30.12,12.5 41.12,12.5 42.82,10.8 43.92,10.8 44.22,11.1 U1.22
  Bottom 0.6: 2.0.P$1 23.62,9.2
P4.0/UCLK  (via drill 0.5)
  Top 0.2: v60.02,18.1 60.02,19 55.02,24 48.92,24 46.32,21.4 44.62,21.4 44.12,21.9 44.12,23.7 43.52,24.3 28.72,24.3 v27.42,23
  Bottom 0.2: U1.29 37.72,15.8 30.88,22.64 27.78,22.64 v27.42,23 27.22,23.2 | v60.02,18.1 60.02,17.9
  Bottom 0.406: RM2.3.1 60.64,17.27 60.02,17.9
  Bottom 0.6: 27.22,23.2 4.0.P$1
P4.1
  Bottom 0.2: U1.30 37.82,16.3 31.02,23.1 29.32,23.1 29.02,23.4
  Bottom 0.6: 29.02,23.4 4.1.P$1
P4.2
  Bottom 0.2: 31.12,23.9 31.12,23.7 38.02,16.8 U1.31
  Bottom 0.6: 31.12,23.9 31.12,24.4 4.2.P$1
P4.3/USTE  (via drill 0.5)
  Top 0.2: v58.92,18.5 58.92,19.4 54.82,23.5 54.72,23.6 49.22,23.6 46.62,21 44.42,21 43.72,21.7 43.72,23.5 43.32,23.9 33.72,23.9 v32.92,23.1
  Bottom 0.2: v32.92,23.1 32.92,22.6 38.22,17.3 U1.32 | RM2.4.1 60.62,18.9 59.32,18.9 v58.92,18.5
  Bottom 0.6: v32.92,23.1 32.92,24.4 4.3.P$1
P4.6
  Bottom 0.2: U1.35 39.92,18.8 37.82,20.9 37.82,22.9 38.02,23.1
  Bottom 0.813: 38.02,23.1 4.6.P$1
P4.7
  Bottom 0.2: 39.52,23.5 38.22,22.2 38.22,21.1 40.02,19.3 U1.36
  Bottom 0.6: 39.52,23.5 39.52,24.4 4.7.P$1
P5.0
  Bottom 0.2: 59.72,20 59.42,19.7 58.22,19.7 57.62,19.1 55.82,19.1 55.12,18.4 52.62,18.4 51.52,17.3 U1.5
  Bottom 0.6: 5.0.P$1 59.72,20.8 59.72,20
P5.1
  Bottom 0.2: 61.52,20.3 60.52,19.3 58.52,19.3 57.92,18.7 56.02,18.7 55.32,18 52.82,18 51.62,16.8 U1.6
  Bottom 0.6: 5.1.P$1 61.52,20.6 61.52,20.3
P6.1
  Bottom 0.2: 53.64,19.93 53.32,19.6 52.02,19.6 51.22,18.8 U1.2
  Bottom 0.5: 53.64,19.93 53.64,20.73 6.1.P$1
P6.2
  Bottom 0.2: 6.2.P$1 56.02,20.7 54.52,19.2 52.22,19.2 51.32,18.3 U1.3
TARGET_PWR  (via drill 0.5)
  Top 0.35: v60.19,14.6 60.42,14.38 60.42,11.8 58.52,9.9 57.82,9.9 53.97,6.05 47.87,6.05 46.32,4.5 v46.32,3.9
  Bottom 0.35: v60.19,14.6 60.42,14.6 60.67,14.85 63.57,14.85 63.82,15.1 64.42,15.1
  Bottom 0.4: PWR_E.1 46.12,4.1 v46.32,3.9
  Bottom 0.5: v60.19,14.6 60.02,14.6 59.62,15 59.43,15 R10.1 R11.1 | BSL.6 65.76,16.45 64.42,15.1
TEST  (via drill 0.5)
  Top 0.2: v32.22,20.2 32.52,19.9 47.42,19.9 v49.72,22.2
  Bottom 0.2: 25.42,23.1 26.28,22.23 30.18,22.23 v32.22,20.2
  Bottom 0.254: U1.47 48.22,21.8 48.62,22.2 v49.72,22.2
  Bottom 0.6: 25.42,23.1 TEST.P$1
USB_SHIELD
  Bottom 0.2: 5.27,21.23 USB.GND3 | USB.GND1 5.27,11.32 | 12.9,21.23 C12.2
  Bottom 0.813: USB.GND3 USB.GND4 | USB.GND1 USB.GND2 | 5.27,11.32 5.27,21.23
  Bottom 1.016: USB.GND4 12.9,21.23
V18
  Bottom 0.2: C7.1 42.31,21.2 42.62,21.2 42.72,21.3 42.72,21.7 44.02,23 45.47,23 46.22,22.25
  Bottom 0.254: 46.22,22.25 U1.43
VCC  (via drill 0.5)
  Top 0.5: v48.52,5.2 54.32,5.2 v57.92,8.8
  Top 0.6: v27.46,14.9 32.82,14.9 | 32.82,14.9 v32.82,15.9 | 32.82,14.9 34.12,13.6 41.82,13.6 47.32,8.1 v48.72,8.1
  Bottom 0.2: C6.2 36.71,15.3 U1.28
  Bottom 0.254: 49.72,12.8 48.92,13.6 48.92,14 49.22,14.3 U1.11
  Bottom 0.4: 19.52,22.5 20.42,22.5 21.52,21.4 23.12,21.4 25.02,19.5 25.02,17.1 26.5,15.62 3.3V_E.2 26.57,15 26.67,14.9 | v32.82,15.9 32.82,16.6 33.52,17.3 35.22,17.3 35.59,16.93 35.59,16.41 C6.2 | L1.1 57.92,11.08 | R8.2 47.41,5.68 PWR_E.2
  Bottom 0.406: C5.2 49.72,5.89 49.72,12.8
  Bottom 0.5: 48.72,5.79 48.72,5.4 v48.52,5.2
  Bottom 0.6: 3.3V.P$1 18.22,23.8 19.52,22.5
  Bottom 0.8: R8.2 48.72,5.79 48.83,5.79 48.92,5.7 C5.2
  Bottom 0.813: v48.72,8.1 48.72,5.79 | 26.67,14.9 v27.46,14.9 | v57.92,8.8 L1.1
VCORE
  Bottom 0.2: C8.1 49.03,3 46.12,3 45.32,3.8 45.32,6 48.72,9.4 U1.13
VOUT
  Bottom 0.2: 20.42,12.85 C2.1
  Bottom 0.4: 25.44,14.87 25.44,15 3.3V_E.1
  Bottom 0.61: VR1.5 20.42,12.85
  Bottom 1.016: C2.1 C3.1 24.61,12.91 25.44,13.74 25.44,14.87
VUSB  (via drill 0.5)
  Top 0.4: USB_BSL.P$2 57.92,27.8 57.92,26 v57.72,25.8
  Bottom 0.254: v57.72,25.8 57.72,24.7 56.52,23.5 51.92,23.5 50.82,22.4 50.82,20.6 50.22,20 49.42,20 48.72,19.3 46.02,19.3 45.72,19.6 U1.42
  Bottom 0.4: v57.72,25.8 58.82,26.9 58.82,30.3 58.42,30.7 57.91,30.7 C11.2

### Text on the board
tNames: 9 | MSP430-BSL | 1 | Rev.B
bNames: RoHS Compliant | (C) 2012 | WWW.OLIMEX.COM/DEV
200bmp: C:/Documents and Settings/user/Desktop/STELLARIS_LOGO135x75MM(600DPI).bmp | C:/Documents and Settings/user/Desktop/STELLARIS_LOGO145x75MM(600DPI).bmp | C:/Documents and Settings/user/Desktop/STELLARIS_LOGO_rgb.bmp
